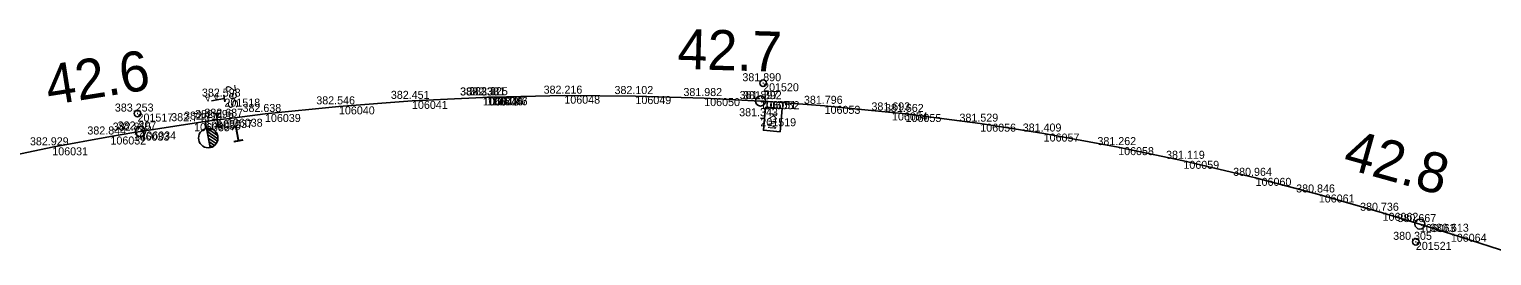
# Model space of a CAD drawing. Extents: x -514522 to -512811, y -1144589 to -1143575.
# Drawn here: x -513234.8 to -513015.5, y -1143609 to -1143575.1 of the extents above; entities that cross this region are included whole.
import ezdxf

# ---------------------------------------------------------------- set-up
doc = ezdxf.new("R2010")
doc.units = 0
for name, color, linetype in [('Vrstva 1', 7, 'Continuous'), ('Vrstva 2', 7, 'Continuous'), ('Vrstva 3', 7, 'Continuous'), ('Vrstva 6', 7, 'Continuous'), ('Vrstva 60', 7, 'Continuous'), ('Vrstva 61', 7, 'Continuous'), ('Vrstva 7', 7, 'Continuous')]:
    doc.layers.add(name, color=color, linetype=linetype)

msp = doc.modelspace()

# ---------------------------------------------------------------- linework, layer by layer
at = {"layer": 'Vrstva 1'}
for p, q in [((-513165.4, -1143585.28), (-513154.53, -1143585.05)), ((-513154.53, -1143585.05), (-513143.87, -1143585.11)), ((-513143.87, -1143585.11), (-513133.56, -1143585.41)), ((-513199.41, -1143587.79), (-513188.32, -1143586.66)), ((-513188.32, -1143586.66), (-513177.37, -1143585.83)), ((-513177.37, -1143585.83), (-513166.73, -1143585.32)), ((-513166.73, -1143585.32), (-513166.04, -1143585.3)), ((-513166.04, -1143585.3), (-513165.4, -1143585.28)), ((-513133.56, -1143585.41), (-513125.13, -1143585.85)), ((-513125.13, -1143585.85), (-513124.64, -1143585.89)), ((-513124.64, -1143585.89), (-513115.51, -1143586.57)), ((-513115.51, -1143586.57), (-513105.41, -1143587.55)), ((-513218.1, -1143590.41), (-513210.04, -1143589.17)), ((-513210.04, -1143589.17), (-513208.38, -1143588.93)), ((-513208.38, -1143588.93), (-513206.58, -1143588.69)), ((-513206.58, -1143588.69), (-513205.12, -1143588.5)), ((-513205.12, -1143588.5), (-513199.41, -1143587.79)), ((-513105.41, -1143587.55), (-513103.37, -1143587.79)), ((-513103.37, -1143587.79), (-513092.17, -1143589.24)), ((-513092.17, -1143589.24), (-513082.67, -1143590.72)), ((-513231.3, -1143592.78), (-513222.58, -1143591.16)), ((-513222.58, -1143591.16), (-513219.1, -1143590.58)), ((-513219.1, -1143590.58), (-513218.1, -1143590.41)), ((-513082.67, -1143590.72), (-513071.5, -1143592.75)), ((-513240.22, -1143594.63), (-513231.3, -1143592.78)), ((-513071.5, -1143592.75), (-513061.72, -1143594.8)), ((-513061.72, -1143594.8), (-513050.89, -1143597.35)), ((-513050.89, -1143597.35), (-513041.42, -1143599.84)), ((-513041.42, -1143599.84), (-513031.86, -1143602.58)), ((-513031.86, -1143602.58), (-513026.27, -1143604.27)), ((-513026.27, -1143604.27), (-513021.63, -1143605.72)), ((-513021.63, -1143605.72), (-513011.36, -1143609))]:
    msp.add_line(p, q, dxfattribs=at)
at = {"layer": 'Vrstva 2'}
for p, q in [((-513208.19, -1143589.94), (-513208.38, -1143588.93)), ((-513208.19, -1143589.94), (-513207.65, -1143592.82)), ((-513208.19, -1143589.94), (-513208.19, -1143589.94)), ((-513207.65, -1143592.82), (-513208.19, -1143589.94)), ((-513208.11, -1143590.36), (-513206.46, -1143591.49)), ((-513208.08, -1143589.93), (-513206.51, -1143591)), ((-513208.01, -1143590.88), (-513206.55, -1143591.88)), ((-513207.91, -1143591.4), (-513206.72, -1143592.22)), ((-513207.82, -1143591.92), (-513206.98, -1143592.5)), ((-513207.72, -1143592.45), (-513207.33, -1143592.72))]:
    msp.add_line(p, q, dxfattribs=at)
msp.add_circle((-513207.92, -1143591.39), 1.46, dxfattribs=at)
msp.add_arc((-513207.92, -1143591.38), 1.46, 280.6292, 100.5901, dxfattribs=at)
at = {"layer": 'Vrstva 3'}
for p, q in [((-513207.16, -1143587.74), (-513206.17, -1143587.65)), ((-513206.99, -1143589.73), (-513205.99, -1143589.64)), ((-513206.66, -1143587.69), (-513206.49, -1143589.69))]:
    msp.add_line(p, q, dxfattribs=at)
at = {"layer": 'Vrstva 6'}
for p, q in [((-513205.41, -1143585.98), (-513205.58, -1143585)), ((-513207.44, -1143585.84), (-513205.49, -1143585.49))]:
    msp.add_line(p, q, dxfattribs=at)
at = {"layer": 'Vrstva 60'}
for p, q in [((-513154.53, -1143585.05), (-513154.53, -1143585.05)), ((-513143.87, -1143585.11), (-513143.87, -1143585.11)), ((-513124.73, -1143583.19), (-513124.73, -1143583.19)), ((-513205.49, -1143585.49), (-513205.49, -1143585.49)), ((-513188.32, -1143586.66), (-513188.32, -1143586.66)), ((-513177.37, -1143585.83), (-513177.37, -1143585.83)), ((-513166.77, -1143585.32), (-513166.77, -1143585.32)), ((-513166.73, -1143585.32), (-513166.73, -1143585.32)), ((-513166.06, -1143585.3), (-513166.06, -1143585.3)), ((-513166.04, -1143585.3), (-513166.04, -1143585.3)), ((-513165.4, -1143585.28), (-513165.4, -1143585.28)), ((-513165.39, -1143585.28), (-513165.39, -1143585.28)), ((-513133.56, -1143585.41), (-513133.56, -1143585.41)), ((-513125.13, -1143585.85), (-513125.13, -1143585.85)), ((-513124.64, -1143585.89), (-513124.64, -1143585.89)), ((-513115.51, -1143586.57), (-513115.51, -1143586.57)), ((-513218.52, -1143587.73), (-513218.52, -1143587.73)), ((-513210.04, -1143589.17), (-513210.04, -1143589.17)), ((-513208.38, -1143588.93), (-513208.38, -1143588.93)), ((-513206.58, -1143588.69), (-513206.58, -1143588.69)), ((-513205.12, -1143588.5), (-513205.12, -1143588.5)), ((-513199.41, -1143587.79), (-513199.41, -1143587.79)), ((-513125.14, -1143588.43), (-513125.14, -1143588.43)), ((-513105.41, -1143587.55), (-513105.41, -1143587.55)), ((-513103.37, -1143587.79), (-513103.37, -1143587.79)), ((-513092.17, -1143589.24), (-513092.17, -1143589.24)), ((-513222.58, -1143591.16), (-513222.58, -1143591.16)), ((-513219.1, -1143590.58), (-513219.1, -1143590.58)), ((-513218.1, -1143590.41), (-513218.1, -1143590.41)), ((-513082.67, -1143590.72), (-513082.67, -1143590.72)), ((-513231.3, -1143592.78), (-513231.3, -1143592.78)), ((-513071.5, -1143592.75), (-513071.5, -1143592.75)), ((-513061.72, -1143594.8), (-513061.72, -1143594.8)), ((-513050.89, -1143597.35), (-513050.89, -1143597.35)), ((-513041.42, -1143599.84), (-513041.42, -1143599.84)), ((-513031.86, -1143602.58), (-513031.86, -1143602.58)), ((-513026.27, -1143604.27), (-513026.27, -1143604.27)), ((-513026.87, -1143606.93), (-513026.87, -1143606.93)), ((-513021.63, -1143605.72), (-513021.63, -1143605.72))]:
    msp.add_line(p, q, dxfattribs=at)
at = {"layer": 'Vrstva 7'}
for p, q in [((-513124.78, -1143583.19), (-513124.68, -1143583.19)), ((-513218.57, -1143587.73), (-513218.47, -1143587.73)), ((-513125.14, -1143588.43), (-513124.52, -1143588.49)), ((-513026.92, -1143606.93), (-513026.82, -1143606.93))]:
    msp.add_line(p, q, dxfattribs=at)
msp.add_lwpolyline([(-513124.37, -1143586.75), (-513121.9, -1143586.97), (-513122.2, -1143590.44), (-513124.68, -1143590.22)], close=True, dxfattribs=at)
for centre, radius in [((-513124.73, -1143583.19), 0.5), ((-513125.13, -1143585.85), 0.75), ((-513218.52, -1143587.73), 0.5), ((-513218.1, -1143590.41), 0.75), ((-513026.27, -1143604.27), 0.75), ((-513026.87, -1143606.93), 0.5)]:
    msp.add_circle(centre, radius, dxfattribs=at)

# ---------------------------------------------------------------- texts
at = {"layer": 'Vrstva 2'}
msp.add_text('1', height=2.5, rotation=10.5807, dxfattribs=at).set_placement((-513204.33, -1143592.12))
at = {"layer": 'Vrstva 6'}
for s, height, rotation, p in [('  A A ', 1, 190, (-513205.67, -1143584.51)), ('Se2', 1.5, 98.4684, (-513203.37, -1143586.87))]:
    msp.add_text(s, height=height, rotation=rotation, dxfattribs=at).set_placement(p)
at = {"layer": 'Vrstva 60'}
for s, p in [('106046', (-513165.4, -1143586.48)), ('106047', (-513165.39, -1143586.48)), ('106048', (-513154.53, -1143586.25)), ('106049', (-513143.87, -1143586.31)), ('201520', (-513124.73, -1143584.39)), ('201518', (-513205.49, -1143586.69)), ('106040', (-513188.32, -1143587.85)), ('106041', (-513177.37, -1143587.03)), ('106042', (-513166.77, -1143586.52)), ('106043', (-513166.73, -1143586.52)), ('106044', (-513166.06, -1143586.5)), ('106045', (-513166.04, -1143586.5)), ('106050', (-513133.56, -1143586.61)), ('106051', (-513125.13, -1143587.05)), ('106052', (-513124.64, -1143587.08)), ('106053', (-513115.51, -1143587.77)), ('201517', (-513218.52, -1143588.93)), ('106035', (-513210.04, -1143590.37)), ('106036', (-513208.38, -1143590.13)), ('106037', (-513206.58, -1143589.89)), ('106038', (-513205.12, -1143589.7)), ('106039', (-513199.41, -1143588.99)), ('201519', (-513125.14, -1143589.63)), ('106054', (-513105.41, -1143588.76)), ('106055', (-513103.37, -1143588.99)), ('106056', (-513092.17, -1143590.44)), ('106032', (-513222.58, -1143592.36)), ('106033', (-513219.1, -1143591.78)), ('106034', (-513218.1, -1143591.61)), ('106057', (-513082.67, -1143591.92)), ('106031', (-513231.3, -1143593.98)), ('106058', (-513071.5, -1143593.95)), ('106059', (-513061.72, -1143596)), ('106060', (-513050.89, -1143598.55)), ('106061', (-513041.42, -1143601.04)), ('106062', (-513031.86, -1143603.78)), ('106063', (-513026.27, -1143605.47)), ('201521', (-513026.87, -1143608.13)), ('106064', (-513021.63, -1143606.92))]:
    msp.add_text(s, height=1.2, dxfattribs=at).set_placement(p)
at = {"layer": 'Vrstva 61'}
for s, p in [('381.890', (-513127.84, -1143582.89)), ('382.598', (-513208.87, -1143585.19)), ('382.546', (-513191.72, -1143586.35)), ('382.451', (-513180.54, -1143585.53)), ('382.338', (-513170.18, -1143585.02)), ('382.338', (-513170.14, -1143585.02)), ('382.331', (-513169.2, -1143585)), ('382.331', (-513169.19, -1143585)), ('382.325', (-513168.81, -1143584.98)), ('382.325', (-513168.8, -1143584.98)), ('382.216', (-513157.64, -1143584.75)), ('382.102', (-513147.01, -1143584.81)), ('381.982', (-513136.68, -1143585.11)), ('381.897', (-513128.25, -1143585.55)), ('381.892', (-513127.75, -1143585.58)), ('381.796', (-513118.61, -1143586.27)), ('383.253', (-513221.92, -1143587.43)), ('382.714', (-513211.55, -1143588.63)), ('382.696', (-513209.89, -1143588.39)), ('382.687', (-513208.5, -1143588.2)), ('382.638', (-513202.78, -1143587.49)), ('381.343', (-513128.32, -1143588.13)), ('381.693', (-513108.49, -1143587.26)), ('381.662', (-513106.46, -1143587.49)), ('382.844', (-513226.04, -1143590.86)), ('382.815', (-513222.24, -1143590.28)), ('382.807', (-513221.5, -1143590.11)), ('382.740', (-513213.47, -1143588.87)), ('381.529', (-513095.29, -1143588.94)), ('381.409', (-513085.81, -1143590.42)), ('382.929', (-513234.65, -1143592.48)), ('381.262', (-513074.61, -1143592.45)), ('381.119', (-513064.32, -1143594.5)), ('380.964', (-513054.26, -1143597.05)), ('380.846', (-513044.81, -1143599.54)), ('380.736', (-513035.23, -1143602.28)), ('380.667', (-513029.62, -1143603.97)), ('380.613', (-513024.74, -1143605.42)), ('380.305', (-513030.27, -1143606.63))]:
    msp.add_text(s, height=1.2, dxfattribs=at).set_placement(p)
at = {"layer": 'Vrstva 7'}
for s, height, rotation, p in [('42.7', 6, 358.2855, (-513137.62, -1143581.03)), ('42.6', 6, 9.0049, (-513231.8, -1143586.51)), ('KM', 1.247, 265, (-513123.82, -1143587.53)), ('42.8', 6, 344.4164, (-513038.02, -1143595.8))]:
    msp.add_text(s, height=height, rotation=rotation, dxfattribs=at).set_placement(p)

doc.saveas('drawing.dxf')
